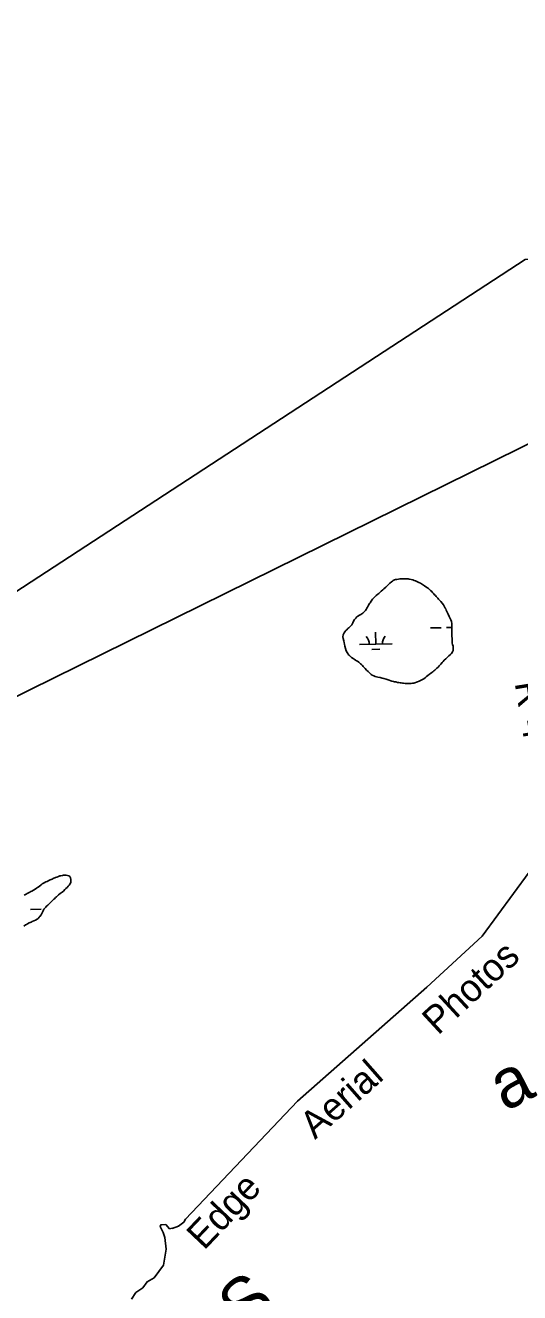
# Model space of a CAD drawing. Extents: x 3957609 to 3995875, y 234277 to 260273.
# Drawn here: x 3963691 to 3965192, y 244464 to 248308 of the extents above; entities that cross this region are included whole.
import ezdxf

# ---------------------------------------------------------------- set-up
doc = ezdxf.new("R2010")
doc.units = 0
for name, color, linetype in [('V-RIVR-EDGE', 7, 'Continuous'), ('V-RIVR-IDEN', 7, 'Continuous'), ('V-RIVR-RANG-IDEN', 7, 'Continuous'), ('V-TOPO-SHOR', 7, 'Continuous'), ('V-UTIL-LINE', 7, 'Continuous'), ('V-WETL-SWMP', 7, 'Continuous')]:
    doc.layers.add(name, color=color, linetype=linetype)

msp = doc.modelspace()

# ---------------------------------------------------------------- linework, layer by layer
at = {"layer": 'V-RIVR-EDGE'}
for points in [[(3964136.99, 244658.589), (3964156.12, 244665.056), (3964172.018, 244677.72), (3964177.945, 244686.611), (3964517.715, 245044.972), (3964910.025, 245389.861), (3965078.158, 245545.06), (3965267.847, 245803.727), (3965776.558, 246139.993), (3966005.855, 246365.518)], [(3964013.541, 244444.268), (3964026.709, 244464.02), (3964047.778, 244478.505), (3964060.946, 244496.941), (3964082.015, 244508.792), (3964110.985, 244546.979), (3964118.885, 244595.701), (3964114.935, 244631.255), (3964109.668, 244645.74), (3964100.45, 244664.175), (3964103.084, 244669.442), (3964117.569, 244670.759), (3964129.42, 244657.591), (3964137.321, 244658.908)]]:
    msp.add_lwpolyline(points, dxfattribs=at)
at = {"layer": 'V-TOPO-SHOR'}
for points in [[(3964985.698, 246454.033), (3964985.792, 246458.563), (3964985.581, 246463.544), (3964985.649, 246470.339), (3964985.571, 246476.68), (3964985.96, 246481.818), (3964986.024, 246489.066), (3964985.667, 246493.443), (3964984.844, 246499.169), (3964982.812, 246504.731), (3964980.957, 246508.332), (3964977.86, 246514.635), (3964974.307, 246521.236), (3964971.663, 246527.546), (3964968.712, 246534.304), (3964967.465, 246537.46), (3964965.92, 246540.16), (3964964.063, 246544.061), (3964960.671, 246549.607), (3964956.985, 246554.696), (3964953, 246559.63), (3964950.853, 246562.321), (3964945.959, 246567.546), (3964943.816, 246569.784), (3964940.298, 246573.518), (3964938.158, 246575.756), (3964936.013, 246578.146), (3964932.798, 246581.73), (3964930.654, 246584.27), (3964927.289, 246587.854), (3964924.846, 246590.088), (3964921.634, 246593.371), (3964919.038, 246595.755), (3964914.919, 246599.177), (3964911.872, 246601.557), (3964906.696, 246604.813), (3964902.744, 246607.183), (3964896.651, 246611.485), (3964890.411, 246615.487), (3964886.007, 246617.547), (3964881.748, 246620.062), (3964875.829, 246622.557), (3964871.882, 246624.32), (3964867.94, 246625.631), (3964862.183, 246627.22), (3964856.586, 246628.06), (3964853.26, 246628.472), (3964847.816, 246629.008), (3964844.042, 246629.113), (3964838.303, 246629.043), (3964834.228, 246628.994), (3964828.19, 246628.768), (3964824.121, 246628.115), (3964818.544, 246627.292), (3964815.233, 246626.495), (3964812.224, 246625.553), (3964808.167, 246623.995), (3964805.47, 246622.301), (3964802.48, 246619.847), (3964798.154, 246615.567), (3964792.932, 246610.521), (3964788.451, 246606.539), (3964785.164, 246603.631), (3964779.786, 246598.884), (3964776.349, 246595.822), (3964771.422, 246591.384), (3964768.135, 246588.626), (3964764.104, 246584.802), (3964761.716, 246582.506), (3964756.635, 246578.066), (3964752.605, 246574.394), (3964749.021, 246571.179), (3964745.298, 246566.907), (3964740.841, 246560.812), (3964738.177, 246556.552), (3964736.247, 246553.81), (3964733.442, 246548.643), (3964730.042, 246542.712), (3964728.418, 246539.672), (3964725.897, 246535.865), (3964723.669, 246532.82), (3964719.64, 246528.845), (3964715.311, 246524.865), (3964709.329, 246520.263), (3964706.179, 246518.564), (3964701.083, 246515.33), (3964698.089, 246513.179), (3964694.204, 246509.81), (3964690.331, 246505.534), (3964688.107, 246502.186), (3964685.621, 246495.663), (3964682.219, 246489.734), (3964679.391, 246486.527), (3964677.154, 246484.235), (3964673.274, 246480.565), (3964670.736, 246478.118), (3964666.857, 246474.294), (3964664.625, 246471.701), (3964661.348, 246467.886), (3964659.566, 246465.449), (3964657.936, 246462.86)], [(3964657.936, 246462.86), (3964656.474, 246459.069), (3964655.335, 246453.316), (3964656.312, 246447.59), (3964658.358, 246440.821), (3964659.343, 246434.342), (3964659.835, 246431.175), (3964661.121, 246424.7), (3964663.326, 246417.177), (3964665.522, 246410.56), (3964667.998, 246405.76), (3964669.847, 246402.61), (3964672.766, 246398.569), (3964675.059, 246396.181), (3964678.877, 246392.755), (3964681.472, 246390.371), (3964686.043, 246386.955), (3964689.088, 246384.878), (3964693.649, 246382.365), (3964696.389, 246380.588), (3964699.277, 246378.962), (3964703.389, 246376.144), (3964705.98, 246374.063), (3964709.187, 246371.081), (3964711.479, 246368.994), (3964714.539, 246365.711), (3964716.683, 246363.321), (3964719.743, 246360.036), (3964722.651, 246356.749), (3964727.089, 246351.973), (3964731.519, 246347.648), (3964734.879, 246344.518), (3964738.238, 246341.541), (3964741.288, 246339.009), (3964744.036, 246336.627), (3964748.74, 246334.571), (3964753.442, 246332.816), (3964756.777, 246331.952), (3964761.473, 246330.649), (3964767.981, 246329.371), (3964774.799, 246327.491), (3964779.038, 246326.486), (3964786.161, 246324.309), (3964792.983, 246322.128), (3964795.863, 246321.255), (3964800.409, 246319.801), (3964803.592, 246318.935), (3964808.591, 246317.636), (3964812.376, 246316.776), (3964816.009, 246316.068), (3964821.305, 246314.923), (3964824.635, 246314.36), (3964829.325, 246313.663), (3964832.35, 246313.247), (3964836.436, 246312.543), (3964839.612, 246311.976), (3964844.601, 246311.584), (3964849.889, 246311.195), (3964853.516, 246311.089), (3964858.646, 246311.152), (3964862.118, 246311.347), (3964866.941, 246312.16), (3964870.103, 246312.801), (3964873.414, 246313.598), (3964878.381, 246315.017), (3964881.84, 246316.117), (3964887.097, 246318.445), (3964890.695, 246320.452), (3964896.395, 246323.543), (3964900.444, 246325.857), (3964905.834, 246329.545), (3964909.123, 246332.153), (3964913.459, 246335.831), (3964917.94, 246339.81), (3964920.782, 246341.809), (3964925.276, 246344.883), (3964928.419, 246347.035), (3964931.109, 246349.485), (3964933.949, 246351.783), (3964937.982, 246355.457), (3964940.669, 246357.904), (3964944.4, 246361.425), (3964947.679, 246364.937), (3964952.144, 246370.276), (3964956.762, 246375.466), (3964959.594, 246378.37), (3964962.871, 246382.034), (3964967.497, 246386.47), (3964972.128, 246390.602), (3964977.207, 246395.194), (3964981.981, 246399.782), (3964984.664, 246402.684), (3964988.08, 246407.406), (3964989.835, 246411.957), (3964990.386, 246416.344), (3964990.478, 246421.026), (3964989.827, 246424.941), (3964988.405, 246430.059), (3964987.304, 246433.819), (3964987.109, 246437.291), (3964986.9, 246441.968)], [(3964986.9, 246441.968), (3964986.714, 246444.985), (3964986.509, 246449.362), (3964985.698, 246454.033)], [(3963686.398, 245575.785), (3963691.737, 245579.248), (3963694.551, 245580.698), (3963697.924, 245582.722), (3963703.269, 245585.62), (3963708.905, 245587.954), (3963712.284, 245589.411), (3963717.075, 245591.452), (3963721.865, 245593.492), (3963727.204, 245596.957), (3963730.01, 245598.973), (3963733.366, 245602.413), (3963735.883, 245604.992), (3963739.224, 245609.848), (3963742.267, 245615.549), (3963745.31, 245621.533), (3963748.075, 245626.948), (3963750.031, 245629.238), (3963753.947, 245633.25), (3963756.183, 245635.544), (3963759.54, 245638.982), (3963764.295, 245643.855), (3963767.652, 245647.293), (3963772.973, 245652.174), (3963778.011, 245657.05), (3963780.528, 245659.628), (3963783.323, 245662.495), (3963785.848, 245664.509), (3963788.642, 245667.658), (3963792.009, 245670.247), (3963797.344, 245673.995), (3963800.148, 245676.295), (3963803.515, 245678.884), (3963806.877, 245681.757), (3963811.352, 245686.342), (3963814.432, 245689.214), (3963818.352, 245692.941), (3963821.424, 245696.378), (3963824.779, 245700.101), (3963827.277, 245704.096), (3963829.198, 245709.216), (3963829.713, 245713.47), (3963829.389, 245716.866), (3963828.471, 245722.236), (3963826.729, 245725.895), (3963823.874, 245727.843), (3963819.612, 245728.924), (3963815.637, 245729.725), (3963812.522, 245729.686), (3963807.709, 245729.629), (3963804.598, 245729.307), (3963799.23, 245728.107), (3963796.123, 245727.503), (3963792.173, 245726.323), (3963786.817, 245724.275), (3963782.59, 245722.524), (3963776.397, 245719.616), (3963772.448, 245718.152), (3963766.534, 245715.53), (3963762.874, 245713.788), (3963757.529, 245710.89), (3963753.58, 245709.425), (3963748.233, 245706.812), (3963742.894, 245703.349), (3963739.244, 245700.754), (3963733.069, 245696.148), (3963728.861, 245692.982), (3963725.211, 245690.387), (3963721.281, 245687.508), (3963715.936, 245684.612), (3963711.445, 245681.442), (3963708.629, 245679.989), (3963705.256, 245677.966), (3963699.06, 245675.06), (3963692.302, 245671.861), (3963688.087, 245669.26)]]:
    msp.add_lwpolyline(points, dxfattribs=at)
at = {"layer": 'V-UTIL-LINE'}
for points in [[(3961767.682, 245361.868), (3961943.705, 245468.964), (3965208.639, 247597.169), (3966396.749, 247622.307), (3967484.854, 247669.667), (3969697.646, 247716.332), (3970569.601, 248052.102), (3971717.759, 248552.062), (3975420.027, 250066.441), (3979384.42, 251663.69), (3984441.626, 253334.756), (3993476.194, 256555.397)], [(3993486.783, 256012.187), (3984358.232, 252707.382), (3984355.815, 252706.645), (3979327.531, 250885.592), (3969939.425, 247110.423), (3969929.75, 247106.755), (3966670.117, 247144.723), (3965413.49, 247134.313), (3961768.13, 245337.826)]]:
    msp.add_lwpolyline(points, dxfattribs=at)
at = {"layer": 'V-WETL-SWMP'}
for p, q in [((3964755.32, 246430.634), (3964754.665, 246466.629)), ((3964921.512, 246480.094), (3964953.507, 246480.676)), ((3964969.504, 246480.967), (3964985.919, 246481.265)), ((3964705.328, 246429.725), (3964805.311, 246431.543)), ((3964743.602, 246414.988), (3964767.598, 246415.424)), ((3963757.528, 245710.89), (3963762.874, 245713.787)), ((3963762.874, 245713.787), (3963766.534, 245715.531)), ((3963766.534, 245715.531), (3963772.449, 245718.152)), ((3963772.449, 245718.152), (3963776.396, 245719.617)), ((3963776.396, 245719.617), (3963782.591, 245722.524)), ((3963782.591, 245722.524), (3963786.817, 245724.275)), ((3963786.817, 245724.275), (3963792.173, 245726.323)), ((3963792.173, 245726.323), (3963796.123, 245727.504)), ((3963796.123, 245727.504), (3963799.231, 245728.108)), ((3963799.231, 245728.108), (3963804.597, 245729.307)), ((3963804.597, 245729.307), (3963807.709, 245729.628)), ((3963807.709, 245729.628), (3963812.522, 245729.687)), ((3963812.522, 245729.687), (3963815.637, 245729.725)), ((3963815.637, 245729.725), (3963819.611, 245728.924)), ((3963819.611, 245728.924), (3963823.873, 245727.843)), ((3963823.873, 245727.843), (3963826.728, 245725.896)), ((3963826.728, 245725.896), (3963828.472, 245722.235)), ((3963828.472, 245722.235), (3963829.388, 245716.866)), ((3963829.712, 245713.471), (3963829.198, 245709.217)), ((3963829.388, 245716.866), (3963829.712, 245713.471)), ((3963692.303, 245671.861), (3963699.061, 245675.059)), ((3963699.061, 245675.059), (3963705.256, 245677.966)), ((3963705.256, 245677.966), (3963708.629, 245679.99)), ((3963708.629, 245679.99), (3963711.444, 245681.441)), ((3963711.444, 245681.441), (3963715.936, 245684.611)), ((3963715.936, 245684.611), (3963721.281, 245687.508)), ((3963721.281, 245687.508), (3963725.211, 245690.388)), ((3963725.211, 245690.388), (3963728.861, 245692.981)), ((3963728.861, 245692.981), (3963733.07, 245696.148)), ((3963733.07, 245696.148), (3963739.244, 245700.755)), ((3963739.244, 245700.755), (3963742.894, 245703.348)), ((3963742.894, 245703.348), (3963748.233, 245706.812)), ((3963748.233, 245706.812), (3963753.581, 245709.426)), ((3963753.581, 245709.426), (3963757.528, 245710.89)), ((3963800.148, 245676.294), (3963797.344, 245673.994)), ((3963803.514, 245678.884), (3963800.148, 245676.294)), ((3963806.878, 245681.757), (3963803.514, 245678.884)), ((3963811.353, 245686.343), (3963806.878, 245681.757)), ((3963814.433, 245689.213), (3963811.353, 245686.343)), ((3963818.352, 245692.942), (3963814.433, 245689.213)), ((3963821.425, 245696.378), (3963818.352, 245692.942)), ((3963824.778, 245700.101), (3963821.425, 245696.378)), ((3963827.278, 245704.096), (3963824.778, 245700.101)), ((3963829.198, 245709.217), (3963827.278, 245704.096)), ((3963688.087, 245669.261), (3963692.303, 245671.861)), ((3963759.54, 245638.982), (3963756.184, 245635.543)), ((3963764.295, 245643.855), (3963759.54, 245638.982)), ((3963767.651, 245647.294), (3963764.295, 245643.855)), ((3963772.972, 245652.174), (3963767.651, 245647.294)), ((3963778.01, 245657.049), (3963772.972, 245652.174)), ((3963780.527, 245659.629), (3963778.01, 245657.049)), ((3963783.324, 245662.495), (3963780.527, 245659.629)), ((3963785.849, 245664.508), (3963783.324, 245662.495)), ((3963788.642, 245667.658), (3963785.849, 245664.508)), ((3963792.009, 245670.248), (3963788.642, 245667.658)), ((3963797.344, 245673.994), (3963792.009, 245670.248)), ((3963707.114, 245626.024), (3963739.109, 245626.606)), ((3963730.01, 245598.973), (3963727.203, 245596.957)), ((3963733.366, 245602.413), (3963730.01, 245598.973)), ((3963735.884, 245604.992), (3963733.366, 245602.413)), ((3963739.223, 245609.848), (3963735.884, 245604.992)), ((3963742.268, 245615.549), (3963739.223, 245609.848)), ((3963745.31, 245621.533), (3963742.268, 245615.549)), ((3963748.076, 245626.948), (3963745.31, 245621.533)), ((3963750.03, 245629.237), (3963748.076, 245626.948)), ((3963753.946, 245633.25), (3963750.03, 245629.237)), ((3963756.184, 245635.543), (3963753.946, 245633.25)), ((3963691.736, 245579.248), (3963686.398, 245575.785)), ((3963694.55, 245580.699), (3963691.736, 245579.248)), ((3963697.924, 245582.722), (3963694.55, 245580.699)), ((3963703.269, 245585.62), (3963697.924, 245582.722)), ((3963708.905, 245587.954), (3963703.269, 245585.62)), ((3963712.285, 245589.411), (3963708.905, 245587.954)), ((3963717.075, 245591.452), (3963712.285, 245589.411)), ((3963721.864, 245593.493), (3963717.075, 245591.452)), ((3963727.203, 245596.957), (3963721.864, 245593.493))]:
    msp.add_line(p, q, dxfattribs=at)
for points in [[(3964656.312, 246447.591), (3964655.336, 246453.317), (3964656.474, 246459.069), (3964657.937, 246462.861), (3964659.566, 246465.448), (3964661.348, 246467.886), (3964664.624, 246471.701), (3964666.857, 246474.295), (3964670.736, 246478.117), (3964673.273, 246480.564), (3964677.154, 246484.235), (3964679.391, 246486.527), (3964682.22, 246489.733), (3964685.621, 246495.663), (3964688.108, 246502.186), (3964690.332, 246505.535), (3964694.205, 246509.81), (3964698.09, 246513.18), (3964701.083, 246515.33), (3964706.178, 246518.563), (3964709.328, 246520.263), (3964715.311, 246524.865), (3964719.641, 246528.844), (3964723.669, 246532.819), (3964725.897, 246535.866), (3964728.417, 246539.672), (3964730.041, 246542.711), (3964733.441, 246548.642), (3964736.247, 246553.81), (3964738.176, 246556.551), (3964740.842, 246560.811), (3964745.298, 246566.906), (3964749.02, 246571.179), (3964752.605, 246574.394), (3964756.636, 246578.067), (3964761.716, 246582.507), (3964764.104, 246584.802), (3964768.134, 246588.626), (3964771.422, 246591.384), (3964776.35, 246595.823), (3964779.786, 246598.884), (3964785.163, 246603.631), (3964788.45, 246606.54), (3964792.931, 246610.52), (3964798.154, 246615.567), (3964802.48, 246619.848), (3964805.47, 246622.3), (3964808.167, 246623.994), (3964812.225, 246625.553), (3964815.233, 246626.496), (3964818.545, 246627.292), (3964824.122, 246628.115), (3964828.191, 246628.768), (3964834.228, 246628.993), (3964838.304, 246629.043), (3964844.041, 246629.113), (3964847.817, 246629.008), (3964853.259, 246628.471), (3964856.586, 246628.059), (3964862.183, 246627.221), (3964867.94, 246625.63), (3964871.882, 246624.32), (3964875.829, 246622.556), (3964881.748, 246620.062), (3964886.007, 246617.547), (3964890.411, 246615.487), (3964896.65, 246611.486), (3964902.743, 246607.182), (3964906.697, 246604.814), (3964911.871, 246601.556), (3964914.92, 246599.177), (3964919.038, 246595.755), (3964921.634, 246593.371), (3964924.845, 246590.088), (3964927.289, 246587.853), (3964930.654, 246584.27), (3964932.799, 246581.73), (3964936.014, 246578.145), (3964938.157, 246575.756), (3964940.298, 246573.517), (3964943.816, 246569.785), (3964945.958, 246567.546), (3964950.853, 246562.321), (3964953, 246559.63), (3964956.986, 246554.696), (3964960.672, 246549.607), (3964964.062, 246544.062), (3964965.921, 246540.159), (3964967.464, 246537.46), (3964968.711, 246534.304), (3964971.662, 246527.546), (3964974.306, 246521.236), (3964977.86, 246514.636), (3964980.957, 246508.332), (3964982.812, 246504.731), (3964984.843, 246499.169), (3964985.668, 246493.442), (3964986.024, 246489.067), (3964985.961, 246481.819), (3964985.571, 246476.68), (3964985.649, 246470.34)], [(3964985.697, 246454.033), (3964986.509, 246449.362), (3964986.714, 246444.986), (3964986.901, 246441.969), (3964987.11, 246437.29), (3964987.303, 246433.82), (3964988.406, 246430.059), (3964989.827, 246424.942), (3964990.479, 246421.025), (3964990.385, 246416.343), (3964989.835, 246411.957), (3964988.079, 246407.406), (3964984.664, 246402.683), (3964981.981, 246399.782), (3964977.206, 246395.194), (3964972.128, 246390.602), (3964967.498, 246386.469), (3964962.871, 246382.033), (3964959.594, 246378.369), (3964956.761, 246375.466), (3964952.144, 246370.276), (3964947.679, 246364.936), (3964944.4, 246361.424), (3964940.668, 246357.905), (3964937.981, 246355.456), (3964933.949, 246351.783), (3964931.108, 246349.484), (3964928.42, 246347.035), (3964925.276, 246344.883), (3964920.783, 246341.808), (3964917.939, 246339.81), (3964913.458, 246335.83), (3964909.124, 246332.153), (3964905.834, 246329.546), (3964900.443, 246325.856), (3964896.395, 246323.542), (3964890.695, 246320.452), (3964887.096, 246318.445), (3964881.84, 246316.116), (3964878.38, 246315.017), (3964873.415, 246313.598), (3964870.103, 246312.802), (3964866.94, 246312.159), (3964862.118, 246311.346), (3964858.647, 246311.152), (3964853.515, 246311.089), (3964849.889, 246311.196), (3964844.6, 246311.584), (3964839.612, 246311.976), (3964836.435, 246312.542), (3964832.349, 246313.247), (3964829.324, 246313.663), (3964824.635, 246314.36), (3964821.306, 246314.923), (3964816.008, 246316.067), (3964812.375, 246316.777), (3964808.59, 246317.637), (3964803.591, 246318.935), (3964800.41, 246319.802), (3964795.862, 246321.256), (3964792.983, 246322.127), (3964786.162, 246324.308), (3964779.038, 246326.486), (3964774.798, 246327.491), (3964767.981, 246329.371), (3964761.472, 246330.65), (3964756.776, 246331.952), (3964753.443, 246332.817), (3964748.741, 246334.571), (3964744.035, 246336.628), (3964741.288, 246339.01), (3964738.238, 246341.54), (3964734.879, 246344.518), (3964731.519, 246347.648), (3964727.088, 246351.973), (3964722.651, 246356.75), (3964719.742, 246360.037), (3964716.682, 246363.321), (3964714.538, 246365.711), (3964711.478, 246368.995), (3964709.188, 246371.081), (3964705.981, 246374.062), (3964703.389, 246376.144), (3964699.277, 246378.962), (3964696.389, 246380.588), (3964693.649, 246382.366), (3964689.089, 246384.878), (3964686.043, 246386.954), (3964681.472, 246390.371), (3964678.876, 246392.755), (3964675.059, 246396.181), (3964672.765, 246398.569), (3964669.847, 246402.61), (3964667.997, 246405.759), (3964665.522, 246410.56), (3964663.327, 246417.177), (3964661.121, 246424.699), (3964659.834, 246431.176), (3964659.343, 246434.341), (3964658.357, 246440.822), (3964656.312, 246447.591)], [(3964985.649, 246470.34), (3964985.581, 246463.544), (3964985.793, 246458.564), (3964985.697, 246454.033)]]:
    msp.add_lwpolyline(points, dxfattribs=at)
for centre, start, end in [((3964700.077, 246430.105), 0.269879, 41.813537), ((3964810.545, 246432.114), 140.269876, 181.813534)]:
    msp.add_arc(centre, 35.246, start, end, dxfattribs=at)

# ---------------------------------------------------------------- texts
at = {"layer": 'V-RIVR-IDEN'}
for s, height, rotation, p in [('Photos', 82.9998, 42.70939, (3964943.678, 245242.482)), ('Aerial', 82.9998, 41.319378, (3964570.603, 244926.481)), ('a', 150, 27.002011, (3965147.039, 245011.79)), ('Edge', 82.9998, 46.525463, (3964233.833, 244589.796)), ('P A S S', 149.9997, 40.1698, (3963923.472, 243970.457))]:
    msp.add_text(s, height=height, rotation=rotation, dxfattribs=at).set_placement(p)
at = {"layer": 'V-RIVR-RANG-IDEN'}
msp.add_text('R-4 ', height=83, rotation=279.309328, dxfattribs=at).set_placement((3965176.399, 246313.135))

doc.saveas('drawing.dxf')
